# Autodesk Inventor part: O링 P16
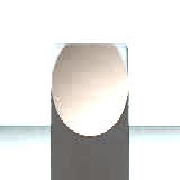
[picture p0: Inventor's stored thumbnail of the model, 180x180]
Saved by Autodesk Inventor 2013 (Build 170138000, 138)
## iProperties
IsCustomPart: 1
Created: 2012-02
Part Number: O링 P16
Material: 고무
Description: O-링
Document SubType Name: Modeling
Standard: JIS 2406
Designer: mdu-01
Standards Organization: JIS
Language: ko-KR
Size Designation: P16
Categories: <MemberInstance><Categories><Category DisplayName="샤프트 부품" InternalName="7f7aeb1f-a693-4053-b835-cee3144e0d98" Mnemonic="SHFT"><Category DisplayName="실링" Intern
Density: 0.93 g/cm^3
Author: mdu-01
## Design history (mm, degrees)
revolve "본체" stored, may be unused: angle "d19" = 90 deg
body "Solid1"
sketch "스케치1"
  geometry: L1 (-0.011, 0)-(-0.011, 0); L2 (-0.663, 2)-(0.663, 2); L3 (-0.663, 0)-(0.663, 0); L4 (-4, -8)-(6.034, -8); L5 (-6.007, 0)-(8.04, 0) reference; L6 (0, 4.64)-(0, -12.44) reference; A1 r 1.2 centre (0, 1) between (-0.663, 2) and (-0.663, 0); A2 r 1.2 centre (0, 1) between (0.663, 0) and (0.663, 2)
  constraints: 8 end point, 4 point on circle, 2 centre point, 2 horizontal alignment, 2 parallel, 1 coincident, 1 horizontal, 1 point on line, 1 other
  dimensions: "d0" = 16 diameter of L5 L4 (= NND); "d1" = 1 distance from line of A1.centre L2 (= -0.25 x NND + 0.25 x NDOR); "d2" = 1.2 radius of A1 (= 0.5 x QDM); "d3" = 1 distance from line of L3 A1.centre (= -0.25 x NND + 0.25 x NDOR); "d4" = 2 distance between parallel lines of L5 L2 (= -0.5 x NND + 0.5 x NDOR)
other parameters: "QDM" = 2.4 [user parameter; used in 1 equation term], "NND" = 16 [user parameter; used in 5 equation terms], "d5" = 0, "d36" = 0, "R2" = 0.2 [user parameter], "NB3" = 6 [user parameter], "SD1" = 15.8 [user parameter], "R1" = 0.4 [user parameter], "NB2" = 4.4 [user parameter], "NB1" = 3.2 [user parameter], "BD" = 16.14 [user parameter], "NTOR" = 2 (= -0.5 x NND + 0.5 x NDOR) [user parameter]
